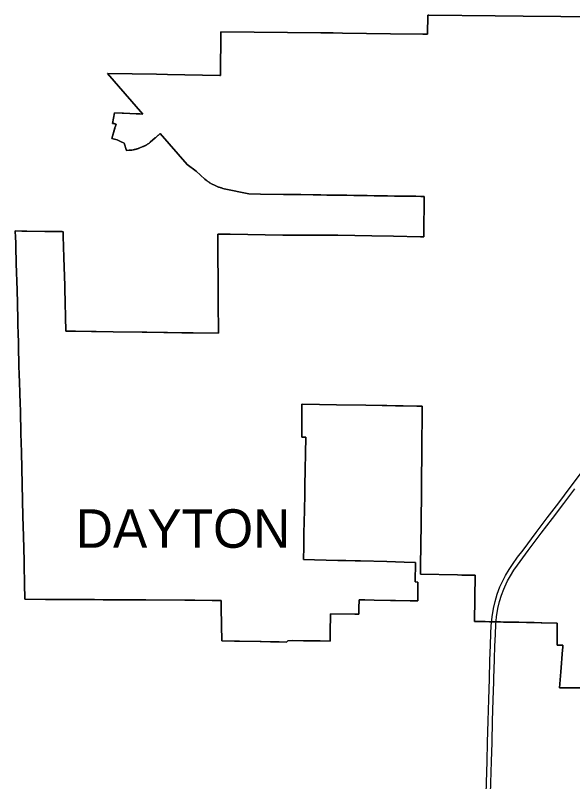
# Model space of a CAD drawing. Extents: x 0 to 34, y 0 to 22.
# Drawn here: x 4.7625 to 4.8789, y 15.159 to 15.3191 of the extents above; entities that cross this region are included whole.
import ezdxf

# ---------------------------------------------------------------- set-up
doc = ezdxf.new("R2010")
doc.units = 0
for name, color, linetype in [('GM_X_Corporation', 7, 'Continuous'), ('GM_X_Corporation_Text', 7, 'Continuous'), ('GM_X_State_Route', 7, 'Continuous')]:
    doc.layers.add(name, color=color, linetype=linetype)

msp = doc.modelspace()

# ---------------------------------------------------------------- linework, layer by layer
at = {"layer": 'GM_X_Corporation'}
for points in [[(4.88121, 15.17862), (4.87617, 15.17867), (4.87642, 15.18199), (4.87677, 15.18655), (4.87681, 15.18709), (4.87682, 15.1872), (4.87684, 15.18753), (4.87642, 15.18753), (4.87563, 15.18755), (4.87563, 15.18779), (4.87565, 15.18922), (4.87567, 15.19133), (4.87568, 15.19184), (4.87568, 15.19216), (4.87247, 15.19223), (4.87234, 15.19223), (4.87086, 15.19226), (4.86925, 15.19229), (4.86765, 15.19233), (4.86743, 15.19233), (4.86604, 15.19236), (4.86529, 15.19238), (4.86443, 15.19239), (4.86382, 15.19241), (4.86286, 15.19243), (4.86213, 15.19244), (4.86191, 15.19245), (4.86153, 15.19245), (4.86064, 15.19247), (4.85864, 15.19251), (4.85839, 15.19251), (4.85852, 15.20215), (4.85735, 15.20217), (4.85575, 15.2022), (4.85483, 15.20222), (4.84709, 15.20235), (4.84713, 15.20482), (4.84717, 15.20783), (4.8473, 15.21931), (4.84731, 15.22028), (4.84732, 15.22165), (4.84734, 15.22301), (4.84738, 15.22666), (4.84738, 15.22683), (4.84743, 15.23092), (4.84746, 15.23426), (4.8475, 15.23748), (4.84726, 15.23749), (4.84722, 15.23749), (4.84677, 15.23749), (4.84637, 15.2375), (4.84351, 15.23755), (4.84191, 15.23757), (4.8401, 15.2376), (4.83915, 15.23762), (4.83572, 15.23767), (4.82957, 15.23777), (4.82605, 15.23783), (4.82238, 15.23788), (4.82235, 15.23788), (4.82233, 15.23458), (4.82233, 15.23378), (4.82231, 15.23098), (4.82317, 15.23097), (4.82298, 15.2208), (4.82295, 15.21917), (4.82288, 15.21568), (4.82279, 15.21095), (4.82273, 15.20766), (4.82269, 15.20589), (4.82268, 15.20544), (4.825, 15.20538), (4.82987, 15.20526), (4.83153, 15.20522), (4.83348, 15.20517), (4.83457, 15.20514), (4.84007, 15.205), (4.84371, 15.20491), (4.84608, 15.20485), (4.84603, 15.20075), (4.84659, 15.20074), (4.84655, 15.1982), (4.84654, 15.19711), (4.84654, 15.19679), (4.84496, 15.19682), (4.84193, 15.19688), (4.84084, 15.19689), (4.83746, 15.19695), (4.83547, 15.19699), (4.83434, 15.19701), (4.83429, 15.19701), (4.83428, 15.19529), (4.83427, 15.194), (4.83343, 15.19401), (4.82832, 15.1941), (4.82829, 15.19016), (4.82827, 15.18842), (4.82616, 15.18845), (4.82479, 15.18847), (4.82468, 15.18847), (4.82456, 15.18847), (4.8239, 15.18848), (4.82266, 15.18849), (4.82042, 15.1885), (4.82037, 15.1885), (4.81943, 15.18848), (4.81914, 15.1882), (4.81761, 15.18823), (4.81623, 15.18826), (4.81577, 15.18827), (4.81385, 15.18831), (4.81364, 15.18831), (4.80932, 15.1884), (4.80877, 15.18841), (4.80828, 15.18842), (4.80563, 15.18847), (4.80557, 15.19176), (4.80549, 15.19542), (4.80547, 15.1969), (4.80361, 15.19691), (4.80003, 15.19693), (4.79791, 15.19694), (4.78975, 15.19699), (4.78629, 15.19701), (4.78551, 15.19702), (4.78361, 15.19703), (4.78268, 15.19704), (4.78084, 15.19705), (4.77907, 15.19706), (4.77182, 15.1971), (4.7688, 15.19712), (4.76454, 15.19714), (4.76445, 15.20043), (4.76442, 15.20198), (4.7644, 15.20264), (4.76434, 15.20518), (4.76421, 15.21032), (4.76411, 15.21441), (4.76379, 15.22784), (4.7637, 15.23175), (4.76367, 15.23268), (4.76361, 15.23552), (4.76359, 15.23625), (4.76353, 15.23825), (4.76348, 15.23996), (4.7634, 15.24273), (4.76336, 15.24383), (4.76329, 15.24618), (4.76319, 15.2497), (4.76318, 15.25011), (4.7631, 15.25329), (4.76308, 15.25382), (4.76302, 15.25643), (4.76298, 15.25801), (4.76295, 15.25899), (4.76289, 15.26171), (4.76272, 15.26726), (4.76262, 15.27078), (4.7626, 15.27164), (4.76256, 15.27272), (4.76252, 15.27405), (4.76389, 15.27402), (4.76493, 15.274), (4.7687, 15.27391), (4.77013, 15.27391), (4.77085, 15.27391), (4.77231, 15.27391), (4.77252, 15.2739), (4.77254, 15.273), (4.77266, 15.26849), (4.77283, 15.26259), (4.77284, 15.26207), (4.77309, 15.25315), (4.77508, 15.25312), (4.77841, 15.25308), (4.77943, 15.25306), (4.78298, 15.25301), (4.78898, 15.25293), (4.78995, 15.25291), (4.79356, 15.25286), (4.7943, 15.25285), (4.79729, 15.25281), (4.79963, 15.25278), (4.80495, 15.2527), (4.8049, 15.25927), (4.8049, 15.25981), (4.80487, 15.26422), (4.80484, 15.26841), (4.80481, 15.27339), (4.80739, 15.27336), (4.81836, 15.27321), (4.82167, 15.2732), (4.82258, 15.2732), (4.82353, 15.27319), (4.82363, 15.27319), (4.82746, 15.27318), (4.82959, 15.27317), (4.82985, 15.27317), (4.83693, 15.27304), (4.84145, 15.27295), (4.84715, 15.27284), (4.84732, 15.27283), (4.8478, 15.27281), (4.8478, 15.27334), (4.84789, 15.28126), (4.84725, 15.28127), (4.84717, 15.28128), (4.84617, 15.28129), (4.84482, 15.28131), (4.8445, 15.28131), (4.84308, 15.28133), (4.84167, 15.28135), (4.84025, 15.28138), (4.83884, 15.2814), (4.83849, 15.2814), (4.83813, 15.28141), (4.83743, 15.28142), (4.83601, 15.28144), (4.8346, 15.28146), (4.83384, 15.28147), (4.83318, 15.28148), (4.83177, 15.2815), (4.83035, 15.28152), (4.82894, 15.28154), (4.82753, 15.28156), (4.82633, 15.28158), (4.82611, 15.28158), (4.8247, 15.2816), (4.82216, 15.28164), (4.82178, 15.28164), (4.81853, 15.28169), (4.81373, 15.28176), (4.81126, 15.2818), (4.80616, 15.28288), (4.80588, 15.28295), (4.80573, 15.28299), (4.80557, 15.28303), (4.80542, 15.28307), (4.80527, 15.28312), (4.80511, 15.28317), (4.80496, 15.28322), (4.80495, 15.28323), (4.80481, 15.28328), (4.80466, 15.28334), (4.80452, 15.2834), (4.80437, 15.28346), (4.80422, 15.28353), (4.80408, 15.2836), (4.80394, 15.28367), (4.80379, 15.28374), (4.80365, 15.28382), (4.80351, 15.28389), (4.80337, 15.28397), (4.80324, 15.28406), (4.8031, 15.28414), (4.80297, 15.28423), (4.80284, 15.28432), (4.80271, 15.28441), (4.80258, 15.28451), (4.80245, 15.2846), (4.80212, 15.28486), (4.80029, 15.28652), (4.80028, 15.28653), (4.79838, 15.28795), (4.79275, 15.29439), (4.79271, 15.29436), (4.79239, 15.29407), (4.79227, 15.29396), (4.79177, 15.29353), (4.79177, 15.29353), (4.79176, 15.29352), (4.79176, 15.29352), (4.79175, 15.29351), (4.79175, 15.29351), (4.79174, 15.2935), (4.79173, 15.29349), (4.79173, 15.29349), (4.79172, 15.29349), (4.7907, 15.2926), (4.79062, 15.29252), (4.79058, 15.29249), (4.79051, 15.29243), (4.79044, 15.29238), (4.79037, 15.29232), (4.79029, 15.29227), (4.79022, 15.29222), (4.79014, 15.29217), (4.79007, 15.29212), (4.78999, 15.29207), (4.78991, 15.29203), (4.78984, 15.29198), (4.78976, 15.29194), (4.78968, 15.29189), (4.7896, 15.29185), (4.78951, 15.29181), (4.78943, 15.29178), (4.78935, 15.29174), (4.78931, 15.29172), (4.78927, 15.2917), (4.78918, 15.29167), (4.78838, 15.29136), (4.78837, 15.29135), (4.78836, 15.29135), (4.78836, 15.29135), (4.78835, 15.29135), (4.78834, 15.29134), (4.78834, 15.29134), (4.78834, 15.29134), (4.78833, 15.29134), (4.78825, 15.29131), (4.78814, 15.29127), (4.78802, 15.29123), (4.78791, 15.29119), (4.78779, 15.29116), (4.78768, 15.29112), (4.78756, 15.29109), (4.78745, 15.29107), (4.78733, 15.29104), (4.78722, 15.29102), (4.78716, 15.291), (4.78715, 15.291), (4.78714, 15.291), (4.78714, 15.291), (4.78713, 15.291), (4.78712, 15.291), (4.78712, 15.291), (4.78711, 15.291), (4.78711, 15.291), (4.7871, 15.29099), (4.78688, 15.29096), (4.78677, 15.29094), (4.78665, 15.29093), (4.78653, 15.29092), (4.78641, 15.29091), (4.78629, 15.2909), (4.78573, 15.29086), (4.78524, 15.29239), (4.78451, 15.29275), (4.78378, 15.29312), (4.78264, 15.29335), (4.78333, 15.29558), (4.78343, 15.29591), (4.78357, 15.29635), (4.78356, 15.29635), (4.78356, 15.29635), (4.78349, 15.29637), (4.78346, 15.29638), (4.78345, 15.29638), (4.78345, 15.29639), (4.78335, 15.29641), (4.78334, 15.29641), (4.78334, 15.29642), (4.78324, 15.29644), (4.78323, 15.29644), (4.78322, 15.29645), (4.78313, 15.29647), (4.78312, 15.29647), (4.78311, 15.29647), (4.78301, 15.2965), (4.78301, 15.2965), (4.783, 15.2965), (4.78288, 15.29652), (4.78284, 15.29653), (4.78283, 15.29653), (4.78282, 15.29653), (4.78323, 15.2987), (4.7848, 15.29864), (4.78508, 15.29863), (4.78773, 15.29854), (4.78778, 15.29853), (4.78851, 15.2985), (4.78912, 15.29848), (4.78917, 15.29848), (4.78175, 15.30697), (4.78178, 15.30697), (4.78186, 15.30697), (4.79201, 15.30678), (4.79427, 15.30674), (4.80522, 15.30655), (4.80534, 15.30655), (4.80546, 15.31564), (4.82629, 15.31543), (4.82721, 15.31542), (4.82888, 15.3154), (4.83081, 15.31537), (4.84086, 15.31526), (4.84762, 15.31519), (4.84784, 15.31518), (4.848, 15.31518), (4.8481, 15.31518), (4.84815, 15.31518), (4.84858, 15.31518), (4.84861, 15.31518), (4.84866, 15.31909), (4.84886, 15.31909), (4.86274, 15.31898), (4.86856, 15.31893), (4.89213, 15.31874)], [(4.89213, 15.31874), (4.86856, 15.31893), (4.86274, 15.31898), (4.84886, 15.31909), (4.84866, 15.31909), (4.84861, 15.31518), (4.84858, 15.31518), (4.84815, 15.31518), (4.8481, 15.31518), (4.848, 15.31518), (4.84784, 15.31518), (4.84762, 15.31519), (4.84086, 15.31526), (4.83081, 15.31537), (4.82888, 15.3154), (4.82721, 15.31542), (4.82629, 15.31543), (4.80546, 15.31564), (4.80534, 15.30655), (4.80522, 15.30655), (4.79427, 15.30674), (4.79201, 15.30678), (4.78186, 15.30697), (4.78178, 15.30697), (4.78175, 15.30697), (4.78916, 15.29848), (4.78912, 15.29848), (4.78851, 15.2985), (4.78778, 15.29853), (4.78773, 15.29854), (4.78508, 15.29863), (4.7848, 15.29864), (4.78323, 15.2987), (4.78282, 15.29653), (4.78283, 15.29653), (4.78284, 15.29653), (4.78288, 15.29652), (4.783, 15.2965), (4.78301, 15.2965), (4.78301, 15.2965), (4.78311, 15.29647), (4.78312, 15.29647), (4.78313, 15.29647), (4.78322, 15.29645), (4.78323, 15.29644), (4.78324, 15.29644), (4.78334, 15.29642), (4.78334, 15.29641), (4.78335, 15.29641), (4.78345, 15.29639), (4.78345, 15.29638), (4.78346, 15.29638), (4.78349, 15.29637), (4.78356, 15.29635), (4.78356, 15.29635), (4.78357, 15.29635), (4.78343, 15.29591), (4.78333, 15.29558), (4.7833, 15.29547), (4.78264, 15.29335), (4.78378, 15.29312), (4.78451, 15.29275), (4.78524, 15.29239), (4.78573, 15.29086), (4.78629, 15.2909), (4.78641, 15.29091), (4.78653, 15.29092), (4.78665, 15.29093), (4.78677, 15.29094), (4.78688, 15.29096), (4.7871, 15.29099), (4.78711, 15.291), (4.78711, 15.291), (4.78712, 15.291), (4.78712, 15.291), (4.78713, 15.291), (4.78714, 15.291), (4.78714, 15.291), (4.78715, 15.291), (4.78716, 15.291), (4.78722, 15.29102), (4.78733, 15.29104), (4.78745, 15.29107), (4.78756, 15.29109), (4.78768, 15.29112), (4.78771, 15.29113), (4.78779, 15.29116), (4.78791, 15.29119), (4.78802, 15.29123), (4.78814, 15.29127), (4.78825, 15.29131), (4.78833, 15.29134), (4.78834, 15.29134), (4.78834, 15.29134), (4.78835, 15.29135), (4.78836, 15.29135), (4.78836, 15.29135), (4.78837, 15.29135), (4.78838, 15.29136), (4.78918, 15.29167), (4.78927, 15.2917), (4.78931, 15.29172), (4.78935, 15.29174), (4.78943, 15.29178), (4.78951, 15.29181), (4.7896, 15.29185), (4.78968, 15.29189), (4.78976, 15.29194), (4.78984, 15.29198), (4.78991, 15.29203), (4.78999, 15.29207), (4.79007, 15.29212), (4.79014, 15.29217), (4.79022, 15.29222), (4.79029, 15.29227), (4.79037, 15.29232), (4.79044, 15.29238), (4.79051, 15.29243), (4.79058, 15.29249), (4.79062, 15.29252), (4.7907, 15.2926), (4.79172, 15.29349), (4.79173, 15.29349), (4.79173, 15.29349), (4.79174, 15.2935), (4.79175, 15.29351), (4.79175, 15.29351), (4.79176, 15.29352), (4.79176, 15.29352), (4.79177, 15.29353), (4.79177, 15.29353), (4.79227, 15.29396), (4.79239, 15.29407), (4.79271, 15.29436), (4.79275, 15.29439), (4.79838, 15.28795), (4.80028, 15.28653), (4.80029, 15.28652), (4.80212, 15.28486), (4.80245, 15.2846), (4.80258, 15.28451), (4.80271, 15.28441), (4.80284, 15.28432), (4.80297, 15.28423), (4.8031, 15.28414), (4.80324, 15.28406), (4.80337, 15.28397), (4.80351, 15.28389), (4.80365, 15.28382), (4.80379, 15.28374), (4.80394, 15.28367), (4.80408, 15.2836), (4.80422, 15.28353), (4.80437, 15.28346), (4.80452, 15.2834), (4.80466, 15.28334), (4.80481, 15.28328), (4.80495, 15.28323), (4.80511, 15.28317), (4.80527, 15.28312), (4.80542, 15.28307), (4.80557, 15.28303), (4.80573, 15.28299), (4.80588, 15.28295), (4.80616, 15.28288), (4.81126, 15.2818), (4.81373, 15.28176), (4.81853, 15.28169), (4.82178, 15.28164), (4.82216, 15.28164), (4.8247, 15.2816), (4.82611, 15.28158), (4.82633, 15.28158), (4.82753, 15.28156), (4.82894, 15.28154), (4.83035, 15.28152), (4.83051, 15.28152), (4.83177, 15.2815), (4.83318, 15.28148), (4.83384, 15.28147), (4.8346, 15.28146), (4.83601, 15.28144), (4.83743, 15.28142), (4.83813, 15.28141), (4.83849, 15.2814), (4.83884, 15.2814), (4.84025, 15.28138), (4.84167, 15.28135), (4.84308, 15.28133), (4.8445, 15.28131), (4.84482, 15.28131), (4.84617, 15.28129), (4.84717, 15.28128), (4.84725, 15.28127), (4.84789, 15.28126), (4.8478, 15.27334), (4.8478, 15.27281), (4.84732, 15.27283), (4.84715, 15.27284), (4.84145, 15.27295), (4.83693, 15.27304), (4.82985, 15.27317), (4.82959, 15.27317), (4.82746, 15.27318), (4.82363, 15.27319), (4.82353, 15.27319), (4.82258, 15.2732), (4.82167, 15.2732), (4.81836, 15.27321), (4.80739, 15.27336), (4.80481, 15.27339), (4.80484, 15.26841), (4.80487, 15.26422), (4.8049, 15.25981), (4.8049, 15.25927), (4.80495, 15.2527), (4.79963, 15.25278), (4.79729, 15.25281), (4.7943, 15.25285), (4.79356, 15.25286), (4.78995, 15.25291), (4.78898, 15.25293), (4.78298, 15.25301), (4.77943, 15.25306), (4.77841, 15.25308), (4.77508, 15.25312), (4.77309, 15.25315), (4.77284, 15.26207), (4.77283, 15.26259), (4.77266, 15.26849), (4.77254, 15.273), (4.77252, 15.2739), (4.77231, 15.27391), (4.77085, 15.27391), (4.77013, 15.27391), (4.7687, 15.27391), (4.7687, 15.27391), (4.76493, 15.274), (4.76389, 15.27402), (4.76252, 15.27405), (4.76256, 15.27272), (4.7626, 15.27164), (4.76262, 15.27078), (4.76272, 15.26726), (4.76289, 15.26171), (4.76295, 15.25899), (4.76298, 15.25801), (4.76302, 15.25643), (4.76308, 15.25382), (4.7631, 15.25329), (4.76318, 15.25011), (4.76318, 15.24993), (4.76319, 15.2497), (4.76329, 15.24618), (4.76336, 15.24383), (4.7634, 15.24273), (4.76348, 15.23996), (4.76353, 15.23825), (4.76359, 15.23625), (4.76361, 15.23552), (4.76367, 15.23268), (4.7637, 15.23175), (4.76379, 15.22784), (4.76411, 15.21441), (4.76421, 15.21032), (4.76434, 15.20518), (4.7644, 15.20264), (4.76442, 15.20198), (4.76445, 15.20043), (4.76454, 15.19714), (4.7688, 15.19712), (4.77182, 15.1971), (4.77907, 15.19706), (4.78084, 15.19705), (4.78268, 15.19704), (4.78361, 15.19703), (4.78551, 15.19702), (4.78629, 15.19701), (4.78975, 15.19699), (4.79791, 15.19694), (4.80003, 15.19693), (4.80361, 15.19691), (4.80547, 15.1969), (4.80549, 15.19542), (4.80557, 15.19176), (4.80563, 15.18847), (4.80828, 15.18842), (4.80877, 15.18841), (4.80932, 15.1884), (4.81364, 15.18831), (4.81385, 15.18831), (4.81577, 15.18827), (4.81623, 15.18826), (4.81761, 15.18823), (4.81914, 15.1882), (4.81943, 15.18848), (4.82037, 15.1885), (4.82042, 15.1885), (4.82266, 15.18849), (4.8239, 15.18848), (4.82456, 15.18847), (4.82468, 15.18847), (4.82479, 15.18847), (4.82616, 15.18845), (4.82827, 15.18842), (4.82829, 15.19016), (4.82832, 15.1941), (4.83343, 15.19401), (4.83427, 15.194), (4.83428, 15.19529), (4.83429, 15.19701), (4.83434, 15.19701), (4.83547, 15.19699), (4.83746, 15.19695), (4.84084, 15.19689), (4.84193, 15.19688), (4.84496, 15.19682), (4.84654, 15.19679), (4.84654, 15.19711), (4.84655, 15.1982), (4.84659, 15.20074), (4.84603, 15.20075), (4.84608, 15.20485), (4.84371, 15.20491), (4.84007, 15.205), (4.83457, 15.20514), (4.83348, 15.20517), (4.83153, 15.20522), (4.82987, 15.20526), (4.825, 15.20538), (4.82268, 15.20544), (4.82269, 15.20589), (4.82273, 15.20766), (4.82279, 15.21095), (4.82288, 15.21568), (4.82295, 15.21917), (4.82298, 15.2208), (4.82317, 15.23097), (4.82231, 15.23098), (4.82233, 15.23378), (4.82233, 15.23458), (4.82235, 15.23788), (4.82238, 15.23788), (4.82605, 15.23783), (4.82957, 15.23777), (4.83572, 15.23767), (4.83915, 15.23762), (4.8401, 15.2376), (4.84191, 15.23757), (4.84351, 15.23755), (4.84637, 15.2375), (4.84677, 15.23749), (4.84722, 15.23749), (4.84726, 15.23749), (4.8475, 15.23748), (4.84746, 15.23426), (4.84743, 15.23092), (4.84738, 15.22683), (4.84738, 15.22666), (4.84734, 15.22301), (4.84732, 15.22165), (4.84731, 15.22028), (4.8473, 15.21931), (4.84717, 15.20783), (4.84713, 15.20482), (4.84709, 15.20235), (4.85483, 15.20222), (4.85575, 15.2022), (4.85735, 15.20217), (4.85852, 15.20215), (4.85839, 15.19251), (4.85864, 15.19251), (4.86064, 15.19247), (4.86153, 15.19245), (4.86191, 15.19245), (4.86213, 15.19244), (4.86286, 15.19243), (4.86382, 15.19241), (4.86443, 15.19239), (4.86529, 15.19238), (4.86604, 15.19236), (4.86743, 15.19233), (4.86765, 15.19233), (4.86925, 15.19229), (4.87086, 15.19226), (4.87234, 15.19223), (4.87247, 15.19223), (4.87568, 15.19216), (4.87568, 15.19184), (4.87567, 15.19133), (4.87565, 15.18922), (4.87563, 15.18779), (4.87563, 15.18755), (4.87642, 15.18753), (4.87684, 15.18753), (4.87682, 15.1872), (4.87681, 15.18709), (4.87677, 15.18655), (4.87642, 15.18199), (4.87617, 15.17867), (4.88121, 15.17862)]]:
    msp.add_lwpolyline(points, dxfattribs=at)
at = {"layer": 'GM_X_State_Route'}
for points in [[(4.86174, 15.18753), (4.86179, 15.18999), (4.86189, 15.19161), (4.86206, 15.19348), (4.86234, 15.19523), (4.86268, 15.19666), (4.86314, 15.19817), (4.86372, 15.19976), (4.86429, 15.20099), (4.86487, 15.20211), (4.86561, 15.20333), (4.86633, 15.20443), (4.8674, 15.20594), (4.86853, 15.20742), (4.87128, 15.21109), (4.87359, 15.21413), (4.87598, 15.21729), (4.87838, 15.22045), (4.88138, 15.22445)], [(4.86452, 15.19923), (4.8647, 15.19971), (4.86532, 15.20098), (4.8659, 15.20202), (4.86664, 15.20323), (4.86734, 15.20427), (4.86961, 15.20733), (4.87234, 15.21094), (4.87467, 15.21403), (4.87703, 15.21714), (4.87936, 15.22022)], [(4.86283, 15.1918), (4.863, 15.19348), (4.8633, 15.19524), (4.86364, 15.19666), (4.86402, 15.19796), (4.86452, 15.19923)], [(4.86269, 15.18837), (4.86282, 15.19163), (4.86283, 15.1918)], [(4.8611, 15.10039), (4.86098, 15.10358), (4.86084, 15.10686), (4.86074, 15.11006), (4.8607, 15.11127), (4.86061, 15.11547), (4.86054, 15.11833), (4.86043, 15.12282), (4.86037, 15.12483), (4.86026, 15.12932), (4.86022, 15.13357), (4.86029, 15.13826), (4.86036, 15.14093), (4.8605, 15.14531), (4.86063, 15.14975), (4.86077, 15.15425), (4.86089, 15.15879), (4.86102, 15.1633), (4.86113, 15.16726), (4.86126, 15.17174), (4.86139, 15.17618), (4.86152, 15.18052), (4.86163, 15.18438), (4.86174, 15.18753)], [(4.86243, 15.17989), (4.86246, 15.18056), (4.86258, 15.18457), (4.86266, 15.18751), (4.86269, 15.18837)], [(4.8617, 15.10886), (4.86166, 15.11004), (4.86163, 15.11126), (4.86153, 15.11545), (4.86147, 15.11831), (4.86136, 15.1228), (4.8613, 15.12474), (4.8612, 15.12929), (4.86114, 15.13355), (4.86121, 15.13824), (4.86128, 15.14091), (4.86142, 15.14529), (4.86155, 15.14973), (4.86169, 15.15423), (4.86181, 15.15877), (4.86194, 15.16328), (4.86206, 15.16724), (4.86218, 15.17172), (4.86232, 15.17616), (4.86243, 15.17989)]]:
    msp.add_lwpolyline(points, dxfattribs=at)

# ---------------------------------------------------------------- texts
at = {"layer": 'GM_X_Corporation_Text'}
msp.add_text('DAYTON', height=0.008037, rotation=0, dxfattribs=at).set_placement((4.77515, 15.20789))

doc.saveas('drawing.dxf')
